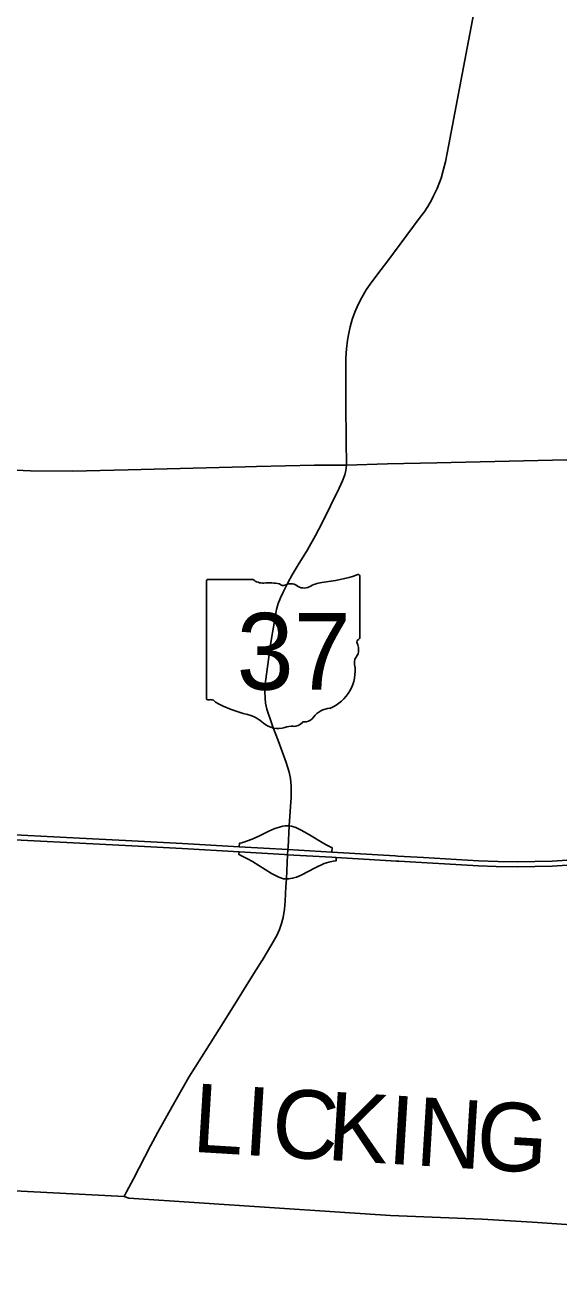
# Model space of a CAD drawing. Extents: x 1853412 to 2125412, y 679418 to 855418.
# Drawn here: x 1954732 to 1962525, y 701178 to 719535 of the extents above; entities that cross this region are included whole.
import ezdxf

# ---------------------------------------------------------------- set-up
doc = ezdxf.new("R2010")
doc.units = 0
for name, color, linetype in [('GM_X_County', 7, 'Continuous'), ('GM_X_County_Text', 7, 'Continuous'), ('GM_X_Interchange_Ramps', 7, 'Continuous'), ('GM_X_State_Location', 7, 'Continuous'), ('GM_X_State_Route', 7, 'Continuous'), ('GM_X_State_Shield', 7, 'Continuous'), ('GM_X_US_Route', 7, 'Continuous'), ('UT_P_Electric', 7, 'Continuous')]:
    doc.layers.add(name, color=color, linetype=linetype)

msp = doc.modelspace()

# ---------------------------------------------------------------- linework, layer by layer
at = {"layer": 'GM_X_County'}
msp.add_lwpolyline([(1991425, 702099), (1978895, 703062), (1976042, 701178), (1970119, 701527), (1969837, 701546), (1969206, 701588), (1968963, 701604), (1967601, 701695), (1967104, 701729), (1966807, 701761), (1966648, 701765), (1966605, 701765), (1965937, 701808), (1964838, 701880), (1963273, 701974), (1962141, 702051), (1961404, 702092), (1960067, 702149), (1959325, 702195), (1956245, 702403), (1956176, 702427), (1945541, 702974)], dxfattribs=at)
at = {"layer": 'GM_X_Interchange_Ramps'}
for points in [[(1959211, 707454), (1959214, 707521), (1959196, 707528), (1959167, 707542)], [(1957855, 707459), (1957852, 707425), (1957874, 707413)]]:
    msp.add_lwpolyline(points, dxfattribs=at)
at = {"layer": 'GM_X_State_Route'}
msp.add_line((1958587, 707838), (1958571, 707528), dxfattribs=at)
for points in [[(1961337, 720001), (1961113, 718821), (1960916, 717791), (1960868, 717539), (1960837, 717411), (1960805, 717299), (1960746, 717149), (1960695, 717044), (1960666, 716978), (1960613, 716888), (1960557, 716803), (1960502, 716728), (1960011, 716072), (1959896, 715923), (1959771, 715750), (1959713, 715667), (1959648, 715557), (1959597, 715455), (1959548, 715340), (1959508, 715236), (1959480, 715129), (1959457, 715035), (1959438, 714934), (1959424, 714805), (1959416, 714677), (1959414, 714554), (1959416, 714001), (1959421, 713469), (1959424, 713106)], [(1959424, 713106), (1959413, 713032), (1959399, 712968), (1959366, 712880), (1959317, 712770), (1959065, 712256), (1958972, 712079), (1958857, 711873), (1958719, 711653), (1958633, 711507), (1958568, 711391), (1958499, 711252), (1958461, 711170), (1958429, 711086), (1958401, 710999), (1958320, 710517), (1958242, 709947), (1958230, 709801), (1958235, 709702), (1958242, 709629), (1958262, 709543), (1958338, 709314), (1958350, 709284)], [(1958350, 709284), (1958427, 709085), (1958544, 708762), (1958587, 708624), (1958607, 708531), (1958615, 708418), (1958616, 708258), (1958587, 707838)], [(1958571, 707528), (1958569, 707492), (1958565, 707417), (1958550, 707064), (1958541, 706952), (1958528, 706738), (1958518, 706623), (1958498, 706500), (1958475, 706415), (1958444, 706323), (1958405, 706235), (1958334, 706112), (1958192, 705871), (1958189, 705867)], [(1958189, 705867), (1958022, 705604), (1957834, 705298), (1957622, 704962), (1957306, 704460), (1957124, 704168), (1956872, 703731), (1956668, 703363), (1956564, 703165)], [(1956564, 703165), (1956313, 702685), (1956212, 702492), (1956177, 702424)]]:
    msp.add_lwpolyline(points, dxfattribs=at)
at = {"layer": 'GM_X_State_Shield'}
for p, q in [((1957378, 711410), (1957378, 709708)), ((1958057, 711439), (1957400, 711439)), ((1959620, 710591), (1959620, 711481)), ((1959620, 710591), (1959620, 710591))]:
    msp.add_line(p, q, dxfattribs=at)
for centre, radius, start, end in [((1957404, 711413), 26, 98.1301, 188.1301), ((1958213, 711636), 252, 231.6195, 271.1119), ((1958297, 710484), 904, 80.4867, 94.9883), ((1958502, 711422), 72.7, 219.7921, 297.1024), ((1958609, 711225), 151, 54.4667, 119.1411), ((1958804, 711495), 182, 233.8562, 294.8282), ((1959125, 710919), 478, 97.3462, 120.7689), ((1958821, 713758), 2377, 275.8445, 288.9065), ((1959595, 711485), 25, 351.8621, 97.738), ((1959614, 710526), 38.6, 107.944, 210.337), ((1959368, 710413), 232, 340.033, 23.6496), ((1959593, 710588), 26.7, 289.6038, 7.7341), ((1959709, 710219), 169, 136.8065, 186.9296), ((1958955, 710105), 595, 292.3089, 8.9858), ((1957404, 709705), 26.2, 171.9584, 258.3066), ((1957408, 709879), 200, 267.339, 280.6039), ((1957449, 709610), 72.1, 29.7484, 93.2717), ((1958359, 711139), 1716, 240.4129, 257.1985), ((1959205, 709231), 326, 94.4031, 142.5768), ((1957848, 708944), 537, 47.1842, 75.836), ((1958428, 709602), 341, 230.7004, 286.2918), ((1958650, 709474), 182, 268.777, 315.5493), ((1958814, 709310), 51.1, 65.7517, 132.6484), ((1958793, 709544), 192, 282.8732, 323.2771), ((1958625, 709014), 280, 85.6951, 111.2099)]:
    msp.add_arc(centre, radius, start, end, dxfattribs=at)
at = {"layer": 'GM_X_US_Route'}
for points in [[(1957943, 713082), (1958112, 713086), (1958958, 713107), (1959424, 713106), (1960023, 713127), (1960745, 713142), (1963489, 713205), (1963851, 713212), (1964440, 713227), (1964609, 713232), (1964772, 713256), (1964914, 713287), (1965242, 713354)], [(1953141, 713106), (1953210, 713102), (1954487, 713037), (1954812, 713024), (1955424, 713021), (1956235, 713039), (1957943, 713082)]]:
    msp.add_lwpolyline(points, dxfattribs=at)
at = {"layer": 'UT_P_Electric'}
for points in [[(1952284, 707752), (1955720, 707577), (1956196, 707551), (1957025, 707508), (1957855, 707459), (1958518, 707420)], [(1952312, 707825), (1955715, 707650), (1956200, 707625), (1957029, 707583), (1957859, 707533), (1958569, 707492), (1959211, 707454), (1960137, 707400), (1960174, 707397)], [(1958587, 707838), (1958532, 707841), (1958496, 707832), (1958445, 707819), (1958379, 707798), (1958289, 707759), (1958144, 707688), (1958045, 707645), (1957978, 707620), (1957923, 707600), (1957907, 707596), (1957895, 707592), (1957862, 707585), (1957859, 707533)], [(1959167, 707542), (1959128, 707562), (1959070, 707594), (1958908, 707694), (1958818, 707748), (1958755, 707783), (1958686, 707816), (1958619, 707836), (1958587, 707838)], [(1960174, 707397), (1960547, 707376), (1961032, 707348), (1961350, 707329), (1961637, 707317), (1961917, 707313), (1962173, 707316), (1962427, 707324), (1962785, 707346), (1963112, 707374), (1963506, 707415), (1963862, 707453), (1964060, 707477), (1964337, 707505), (1964973, 707574), (1965452, 707622), (1965516, 707629)], [(1960186, 707322), (1961351, 707256), (1961611, 707245), (1961920, 707240), (1962425, 707251), (1962792, 707275), (1963138, 707304), (1963565, 707347), (1964001, 707394), (1965459, 707551), (1965528, 707559)], [(1957874, 707413), (1957921, 707387), (1957980, 707359), (1958053, 707319), (1958329, 707144), (1958434, 707091), (1958506, 707065), (1958550, 707064)], [(1958518, 707420), (1958565, 707417), (1959208, 707380), (1959275, 707378), (1960154, 707324), (1960186, 707322)], [(1958550, 707064), (1958579, 707063), (1958636, 707073), (1958694, 707090), (1958762, 707120), (1958966, 707226), (1959100, 707287), (1959168, 707307), (1959231, 707323), (1959273, 707328), (1959275, 707378)]]:
    msp.add_lwpolyline(points, dxfattribs=at)

# ---------------------------------------------------------------- texts
at = {"layer": 'GM_X_County_Text'}
for s, rotation, p in [('L', 356.5017, (1957159, 703080)), ('I', 356.5014, (1957905, 703034)), ('C', 356.5017, (1958314, 703009)), ('K', 356.5016, (1959126, 702960)), ('I', 356.5015, (1960009, 702906)), ('N', 356.5016, (1960418, 702881)), ('G', 356.5017, (1961300, 702827))]:
    msp.add_text(s, height=1000, rotation=rotation, dxfattribs=at).set_placement(p)
at = {"layer": 'GM_X_State_Location'}
msp.add_text('37', height=1, rotation=0, dxfattribs=at).set_placement((1958088, 710428))
for s in ['s', 'r']:
    msp.add_text(s, height=1, dxfattribs=at).set_placement((1958340, 710501))
at = {"layer": 'GM_X_State_Shield'}
msp.add_text('37', height=1120.7, dxfattribs=at).set_placement((1957820, 709828))

doc.saveas('drawing.dxf')
